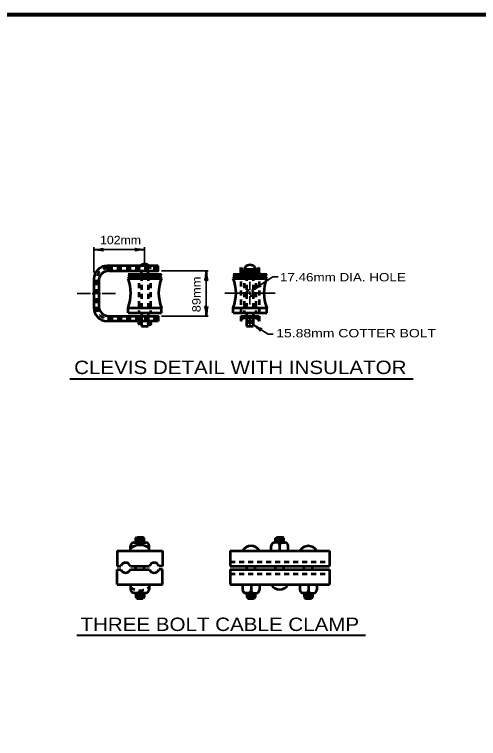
# Model space of a CAD drawing. Extents: x -34 to 821, y -14 to 530.
# Drawn here: x 257.5 to 424.1, y 264 to 523.9 of the extents above; entities that cross this region are included whole.
import ezdxf

# ---------------------------------------------------------------- set-up
doc = ezdxf.new("R2010")
doc.units = 0
doc.header["$LTSCALE"] = 1.2
doc.linetypes.add('SHORT_DASHED', pattern=[2.7, 1.5, -1.2])
doc.layers.add('1', color=7, linetype='Continuous', lineweight=53)

msp = doc.modelspace()

# ---------------------------------------------------------------- linework, layer by layer
at = {"layer": '1', "lineweight": 35}
for p, q in [((285.93, 431.298), (285.93, 440.312)), ((285.93, 439.48), (304.171, 439.48)), ((304.171, 434.912), (304.171, 440.312)), ((310.231, 431.853), (327.031, 431.853)), ((326.344, 415.646), (326.344, 431.853)), ((342.031, 427.953), (342.031, 424.983)), ((279.93, 423.749), (284.731, 423.749)), ((285.331, 423.749), (288.331, 423.749)), ((288.93, 423.749), (293.731, 423.749)), ((340.873, 423.903), (333.031, 423.903)), ((342.031, 423.903), (341.43, 423.903)), ((342.031, 424.503), (342.031, 423.303)), ((342.631, 423.903), (342.031, 423.903)), ((351.031, 423.903), (343.19, 423.903)), ((342.031, 422.823), (342.031, 419.853)), ((310.248, 415.646), (327.048, 415.646)), ((342.031, 412.346), (342.031, 414.753))]:
    msp.add_line(p, q, dxfattribs=at)
at = {"layer": '1'}
for p, q in [((309.031, 433.653), (290.731, 433.653)), ((303.031, 430.653), (303.031, 431.853)), ((305.43, 430.653), (305.43, 431.853)), ((338.731, 431.253), (338.731, 433.053)), ((338.731, 433.053), (339.631, 431.853)), ((339.631, 431.853), (344.43, 431.853)), ((339.93, 432.453), (344.131, 432.453)), ((344.43, 431.853), (345.331, 433.053)), ((345.331, 431.253), (345.331, 433.053)), ((285.93, 428.853), (285.93, 418.646)), ((298.231, 430.653), (310.231, 430.653)), ((298.231, 430.653), (298.831, 430.053)), ((298.231, 429.153), (298.831, 430.053)), ((298.231, 429.153), (310.231, 429.153)), ((298.831, 430.053), (309.631, 430.053)), ((310.231, 430.653), (309.631, 430.053)), ((310.231, 429.153), (309.631, 430.053)), ((336.031, 430.653), (348.031, 430.653)), ((336.031, 430.653), (336.631, 430.053)), ((336.031, 429.153), (336.631, 430.053)), ((336.031, 429.153), (348.031, 429.153)), ((336.631, 430.053), (347.43, 430.053)), ((338.731, 431.253), (345.331, 431.253)), ((340.831, 430.653), (340.831, 431.253)), ((343.231, 430.653), (343.231, 431.253)), ((348.031, 430.653), (347.43, 430.053)), ((348.031, 429.153), (347.43, 430.053)), ((287.731, 428.253), (287.731, 419.246)), ((298.231, 418.653), (310.231, 418.653)), ((298.231, 416.853), (298.231, 418.653)), ((310.231, 416.853), (310.231, 418.653)), ((336.031, 418.653), (348.031, 418.653)), ((336.031, 416.853), (336.031, 418.653)), ((348.031, 416.853), (348.031, 418.653)), ((298.231, 416.853), (310.231, 416.853)), ((303.031, 416.853), (303.031, 415.646)), ((305.43, 416.853), (305.43, 415.646)), ((336.031, 416.853), (348.031, 416.853)), ((340.831, 416.853), (340.831, 415.653)), ((343.231, 416.853), (343.231, 415.653)), ((309.048, 413.846), (290.731, 413.846)), ((303.031, 413.846), (303.031, 412.046)), ((305.43, 413.846), (305.43, 412.046)), ((338.731, 415.653), (345.331, 415.653)), ((338.731, 415.653), (338.731, 413.853)), ((338.731, 413.853), (339.631, 415.053)), ((339.631, 415.053), (344.43, 415.053)), ((340.831, 415.053), (340.831, 412.046)), ((343.231, 415.053), (343.231, 412.046)), ((344.43, 415.053), (345.331, 413.853)), ((345.331, 415.653), (345.331, 413.853)), ((302.43, 412.946), (301.781, 412.571)), ((303.031, 412.046), (305.43, 412.046)), ((340.831, 412.046), (343.231, 412.046)), ((301.002, 335.888), (301.434, 336.32)), ((301.002, 335.888), (304.026, 335.888)), ((301.002, 334.376), (301.002, 335.888)), ((301.434, 336.32), (303.594, 336.32)), ((301.914, 335.408), (303.114, 335.408)), ((304.026, 335.888), (303.594, 336.32)), ((304.026, 334.376), (304.026, 335.888)), ((351.21, 335.888), (351.618, 336.32)), ((351.21, 334.376), (351.21, 335.888)), ((351.21, 335.888), (354.234, 335.888)), ((351.618, 336.32), (353.802, 336.32)), ((352.098, 335.408), (353.322, 335.408)), ((354.234, 335.888), (353.802, 336.32)), ((354.234, 334.376), (354.234, 335.888)), ((299.178, 331.352), (299.178, 333.176)), ((300.402, 334.376), (304.626, 334.376)), ((301.002, 334.928), (304.026, 334.928)), ((305.85, 331.352), (305.85, 333.176)), ((349.698, 331.352), (349.698, 333.176)), ((352.722, 334.376), (350.898, 334.376)), ((351.21, 334.928), (354.234, 334.928)), ((352.722, 334.376), (354.522, 334.376)), ((352.722, 331.352), (352.722, 333.464)), ((355.746, 331.352), (355.746, 333.176)), ((294.354, 331.352), (310.674, 331.352)), ((294.354, 331.352), (294.354, 325.904)), ((310.674, 331.352), (310.674, 325.904)), ((334.866, 331.352), (370.554, 331.352)), ((334.866, 331.352), (334.866, 325.904)), ((370.554, 331.352), (370.554, 325.904)), ((294.354, 325.904), (295.65, 325.904)), ((299.082, 325.904), (305.946, 325.904)), ((301.002, 324.704), (301.002, 325.904)), ((304.026, 324.704), (304.026, 325.904)), ((310.674, 325.904), (309.354, 325.904)), ((334.866, 325.904), (370.554, 325.904)), ((340.914, 324.704), (340.914, 325.904)), ((343.938, 324.704), (343.938, 325.904)), ((351.21, 324.704), (351.21, 325.904)), ((354.234, 324.704), (354.234, 325.904)), ((361.482, 324.704), (361.482, 325.904)), ((364.506, 324.704), (364.506, 325.904)), ((294.354, 319.256), (294.354, 324.704)), ((294.354, 324.704), (295.65, 324.704)), ((299.082, 324.704), (305.922, 324.704)), ((310.674, 324.704), (309.354, 324.704)), ((310.674, 319.256), (310.674, 324.704)), ((334.866, 324.704), (334.866, 319.256)), ((370.554, 324.704), (370.554, 319.256)), ((294.354, 319.256), (310.674, 319.256)), ((299.178, 319.304), (299.178, 317.504)), ((305.85, 319.304), (305.85, 317.504)), ((334.866, 319.256), (370.554, 319.256)), ((339.378, 319.28), (339.378, 317.456)), ((342.402, 319.28), (342.402, 317.144)), ((345.426, 319.28), (345.426, 317.456)), ((359.994, 319.256), (359.994, 317.432)), ((363.018, 319.256), (363.018, 317.144)), ((366.042, 319.256), (366.042, 317.432)), ((300.402, 316.28), (304.626, 316.28)), ((301.002, 316.28), (301.002, 314.768)), ((301.002, 315.752), (304.026, 315.752)), ((301.002, 314.768), (301.434, 314.336)), ((301.002, 314.768), (304.026, 314.768)), ((301.914, 315.248), (303.114, 315.248)), ((304.026, 314.768), (303.594, 314.336)), ((304.026, 316.28), (304.026, 314.768)), ((342.402, 316.256), (340.602, 316.256)), ((340.89, 316.256), (340.89, 314.744)), ((340.89, 315.704), (343.914, 315.704)), ((340.89, 314.744), (341.322, 314.312)), ((340.89, 314.744), (343.914, 314.744)), ((341.802, 315.224), (343.026, 315.224)), ((342.402, 316.256), (344.226, 316.256)), ((343.914, 314.744), (343.506, 314.312)), ((343.914, 316.256), (343.914, 314.744)), ((363.018, 316.232), (361.194, 316.232)), ((361.506, 316.232), (361.506, 314.72)), ((361.506, 315.68), (364.53, 315.68)), ((361.506, 314.72), (361.938, 314.288)), ((361.506, 314.72), (364.53, 314.72)), ((362.418, 315.2), (363.618, 315.2)), ((363.018, 316.232), (364.842, 316.232)), ((364.53, 314.72), (364.098, 314.288)), ((364.53, 316.232), (364.53, 314.72)), ((301.434, 314.336), (303.594, 314.336)), ((341.322, 314.312), (343.506, 314.312)), ((361.938, 314.288), (364.098, 314.288))]:
    msp.add_line(p, q, dxfattribs=at)
at = {"layer": '1', "linetype": 'SHORT_DASHED'}
for p, q in [((309.031, 432.753), (291.031, 432.753)), ((302.131, 430.653), (302.131, 416.853)), ((303.031, 430.053), (303.031, 416.853)), ((305.43, 430.053), (305.43, 416.853)), ((306.331, 430.653), (306.331, 416.853)), ((338.731, 431.253), (338.731, 415.653)), ((339.93, 430.653), (339.93, 416.853)), ((340.831, 430.053), (340.831, 416.853)), ((343.231, 430.053), (343.231, 416.853)), ((344.131, 430.653), (344.131, 416.853)), ((345.331, 431.253), (345.331, 415.653)), ((286.831, 428.553), (286.831, 418.946)), ((309.048, 414.746), (291.031, 414.746)), ((303.031, 415.646), (303.031, 413.846)), ((305.43, 415.646), (305.43, 413.846)), ((334.866, 327.416), (370.554, 327.416)), ((334.866, 323.192), (370.554, 323.192))]:
    msp.add_line(p, q, dxfattribs=at)
at = {"layer": '1', "lineweight": 40}
for p, q in [((277.394, 393.136), (400.616, 393.136)), ((279.908, 301.112), (383.578, 301.112))]:
    msp.add_line(p, q, dxfattribs=at)
at = {"layer": '1', "lineweight": 13}
msp.add_line((299.082, 325.904), (299.178, 325.904), dxfattribs=at)
at = {"layer": '1', "lineweight": 158}
msp.add_lwpolyline([(814.88, 523.876), (23.18, 523.776), (23.28, -2.224)], dxfattribs=at)
at = {"layer": '1'}
for points in [[(291.331, 431.853), (309.031, 431.853), (309.031, 433.653)], [(291.331, 415.646), (309.048, 415.646), (309.048, 413.846)], [(303.031, 412.946), (302.43, 412.946), (301.781, 413.321)], [(334.866, 324.704), (340.914, 324.704), (343.938, 324.704), (361.482, 324.704)], [(361.482, 324.704), (364.506, 324.704), (370.554, 324.704)]]:
    msp.add_lwpolyline(points, dxfattribs=at)
at = {"layer": '1', "lineweight": 35}
for points in [[(342.748, 424.817), (350.3, 429.756), (352.17, 429.756)], [(343.231, 412.546), (348.554, 409.093), (350.341, 409.093)]]:
    msp.add_lwpolyline(points, dxfattribs=at)
at = {"layer": '1', "linetype": 'SHORT_DASHED'}
msp.add_circle((342.031, 423.906), 1.159, dxfattribs=at)
at = {"layer": '1'}
for centre in [(305.975, 412.934), (342.022, 413.546)]:
    msp.add_circle(centre, 0.539, dxfattribs=at)
for centre, radius, start, end in [((304.231, 432.119), 2.193, 44.35198, 135.64802), ((342.031, 431.819), 2.193, 44.35198, 135.64802), ((290.731, 428.853), 4.8, 90, 180), ((291.331, 428.253), 3.6, 90, 180), ((342.031, 431.819), 2.193, 135.64802, 163.217), ((342.031, 431.819), 2.193, 16.783, 44.35198), ((284.812, 423.903), 14.409, 338.63221, 21.36779), ((323.649, 423.903), 14.409, 158.63221, 201.36779), ((322.612, 423.903), 14.409, 338.63221, 21.36779), ((361.449, 423.903), 14.409, 158.63221, 201.36779), ((290.731, 418.646), 4.8, 180, 270), ((291.331, 419.246), 3.6, 180, 270), ((300.397, 333.172), 1.21, 90, 180), ((302.513, 328.296), 5.179, 50.03379, 129.96621), ((300.908, 333.059), 1.658, 14.49718, 52.88295), ((304.11, 333.059), 1.658, 127.11705, 165.50282), ((304.63, 333.172), 1.21, 0, 90), ((342.413, 329.68), 3.462, 29.14172, 150.85828), ((350.897, 333.172), 1.21, 90, 180), ((351.647, 333.419), 1.066, 2.94427, 64.43586), ((353.777, 333.419), 1.066, 115.56414, 177.05572), ((354.526, 333.172), 1.21, 0, 90), ((363.016, 329.667), 3.462, 29.14172, 150.85828), ((297.367, 325.309), 1.814, 19.49795, 160.50177), ((307.645, 325.306), 1.814, 19.58943, 160.41041), ((297.367, 325.309), 1.814, 199.44421, 340.55538), ((307.645, 325.306), 1.814, 199.35299, 340.6469), ((300.397, 317.497), 1.21, 180, 270), ((300.908, 317.609), 1.658, 307.11705, 345.50282), ((304.11, 317.609), 1.658, 194.49718, 232.88295), ((304.63, 317.497), 1.21, 270, 0), ((340.599, 317.456), 1.21, 180, 270), ((341.349, 317.208), 1.066, 295.56414, 357.05572), ((343.478, 317.208), 1.066, 182.94428, 244.43586), ((344.228, 317.456), 1.21, 270, 0), ((352.712, 320.947), 3.462, 209.14172, 330.85828), ((361.202, 317.443), 1.21, 180, 270), ((361.951, 317.195), 1.066, 295.56414, 357.05572), ((364.081, 317.195), 1.066, 182.94428, 244.43586), ((364.83, 317.443), 1.21, 270, 0)]:
    msp.add_arc(centre, radius, start, end, dxfattribs=at)
at = {"layer": '1', "linetype": 'SHORT_DASHED'}
for centre, radius, start, end in [((291.031, 428.553), 4.2, 90, 180), ((304.231, 432.119), 2.193, 135.64802, 163.217), ((304.231, 432.119), 2.193, 16.783, 44.35198), ((291.031, 418.946), 4.2, 180, 270), ((302.513, 322.373), 5.179, 230.03379, 309.96621)]:
    msp.add_arc(centre, radius, start, end, dxfattribs=at)
at = {"layer": '1', "lineweight": 13}
msp.add_arc((297.367, 325.309), 1.814, 199.26221, 340.15338, dxfattribs=at)
at = {"layer": '1', "lineweight": 40}
for centre, major_axis, ratio, start_param, end_param in [((287.275, 439.226), (-2.108, 0.211), 0.07063, 3.1407148, 5.41811), ((287.24, 439.811), (-2.143, -0.187), 0.122415, 0.8963533, 3.1415927), ((302.861, 439.148), (2.143, 0.187), 0.122415, 0.8963533, 3.1415927), ((302.826, 439.733), (2.108, -0.211), 0.07063, 3.1407148, 5.41811), ((326.09, 430.508), (0.211, 2.108), 0.07063, 3.1407148, 5.41811), ((326.675, 430.543), (-0.187, 2.143), 0.122415, 0.8963533, 3.1415927), ((343.662, 425.811), (-1.691, -1.33), 0.122415, 0.8963533, 3.1415927), ((344.012, 425.34), (1.879, 0.977), 0.07063, 6.2823074, 8.5597026), ((326.012, 416.955), (0.187, -2.143), 0.122415, 0.8963533, 3.1415927), ((326.598, 416.99), (-0.211, -2.108), 0.07063, 3.1407148, 5.41811), ((344.22, 411.601), (-1.654, 1.324), 0.07063, 3.1407148, 5.41811), ((344.51, 412.112), (-1.9, 1.009), 0.122415, 0.8963533, 3.1415927)]:
    msp.add_ellipse(centre, major_axis=major_axis, ratio=ratio, start_param=start_param, end_param=end_param, dxfattribs=at)

# ---------------------------------------------------------------- texts
at = {"layer": '1'}
for s, height, width, p in [('102mm', 3, 1.1, (288.192, 441.443)), ('17.46mm DIA. HOLE', 3, 1.2, (352.794, 428.093)), ('15.88mm COTTER BOLT', 3, 1.25, (351.464, 408.012)), ('CLEVIS DETAIL WITH INSULATOR', 4.8, 1.15, (278.882, 394.836)), ('THREE BOLT CABLE CLAMP', 4.8, 1.15, (281.15, 302.625))]:
    msp.add_text(s, height=height, dxfattribs=dict(at, width=width)).set_placement(p)
at = {"layer": '1', "width": 1.15}
msp.add_text('89mm', height=3, rotation=90, dxfattribs=at).set_placement((324.281, 417.006))

doc.saveas('drawing.dxf')
